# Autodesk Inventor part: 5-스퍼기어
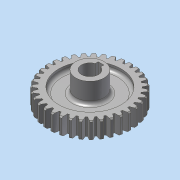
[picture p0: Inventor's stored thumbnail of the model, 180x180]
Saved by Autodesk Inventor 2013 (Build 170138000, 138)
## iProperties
Created: 2013-08
Part Number: 5-스퍼기어
Material: 강
Document SubType Name: Modeling
Designer: 한국산업디자인학원
Categories: <?xml version="1.0" encoding="UTF-16"?> <MemberInstance><Categories><FamilyTemplate><FamilyTemplateParameter ValueType="xs:double" Id="1" ObjectReferenceKey="da
Density: 1 g/cm^3
CustomPartVersion: 1
Author: 한국산업디자인학원
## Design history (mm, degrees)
sketch "Sketch1"
  geometry: C1 r 37 at (0, 0)
  constraints: 1 centre point
  dimensions: "d0" = 74 diameter of C1 (= da_da)
extrude "Extrusion1" new body sketch "Sketch1" distance "d1" = 15; taper "d2" = 0 deg
chamfer "모따기1" distance "d49" = 1; stored, may be unused: second distance "d50" = 2, angle "d51" = 45 deg
node "작업 평면11"
sketch "스케치3"
  geometry: C1 r 12.5 at (0, 0); 1 further point
  constraints: 1 centre point, 1 coincident
  dimensions: "d53" = 25 diameter of C1
extrude "돌출2" join sketch "스케치3" distance "d55" = 31; taper "d56" = 0 deg
sketch "스케치4"
  geometry: C1 r 12.5 at (0, 0) reference; C2 r 36 at (0, 0) reference; C3 r 27.5 at (0, 0)
  constraints: 1 centre point, 1 coincident
  dimensions: "d57" = 55 diameter of C3
extrude "돌출3" cut sketch "스케치4" distance "d59" = 5; taper "d60" = 0 deg
sketch "스케치5"
  geometry: C1 r 12.5 at (0, 0); C2 r 36 at (0, 0); C3 r 27.5 at (0, 0)
  constraints: 3 centre point, 1 coincident
  dimensions: "d61" = 55 diameter of C3
extrude "돌출4" cut sketch "스케치5" taper "d63" = 0 deg; distance "d64" = 5
fillet "모깎기1" dims "d65" = 3
sketch "스케치6" dims "d66" = 15
  geometry: L1 (2.5, 5.2)-(-2.5, 5.2); L2 (-2.5, 5.2)-(-2.5, 9.8); L3 (-2.5, 9.8)-(2.5, 9.8); L4 (2.5, 9.8)-(2.5, 5.2); L5 (2.5, 5.2)-(-2.5, 9.8); L6 (-2.5, 5.2)-(2.5, 9.8); C1 r 12.5 at (0, 0) reference; 3 further points
  constraints: 12 end point, 3 midpoint, 2 parallel, 2 vertical alignment, 1 coincident, 1 horizontal, 1 perpendicular, 2 other
  dimensions: "d68" = 5 distance of L2.end L3.end; "d69" = 17.3 dimension on L3
extrude "돌출5" cut sketch "스케치6" stored distance "d70" = 5; taper "d71" = 0 deg
workplane "Work Plane2"
feature "피치 지름" dims "d4" = 10, "d5" = 0
workplane "Work Plane8"
workplane "Work Plane9"
feature "스퍼 기어" dims "da_b" = 15, "da_d" = 70, "da_aw" = 70, "da_da" = 74, "da_df" = 65, "da_dw" = 70, angle "da_beta" = 0 deg, "da_lefttooth" = 0, "da_righttooth" = 0
body "Solid1"
sketch "Sketch2"
  geometry: C1 r 37 at (0, 0) reference; C2 r 35 at (0, 0)
  constraints: 1 centre point, 1 coincident
  dimensions: "d3" = 70 diameter of C2 (= da_dw)
body "Srf1"
other parameters: "d17" = 0, "d34" = 0.8976 (computed from da_z), "d39" = 0, "d41" = 0, "d47" = 0, "d48" = 0, "d52" = 3
